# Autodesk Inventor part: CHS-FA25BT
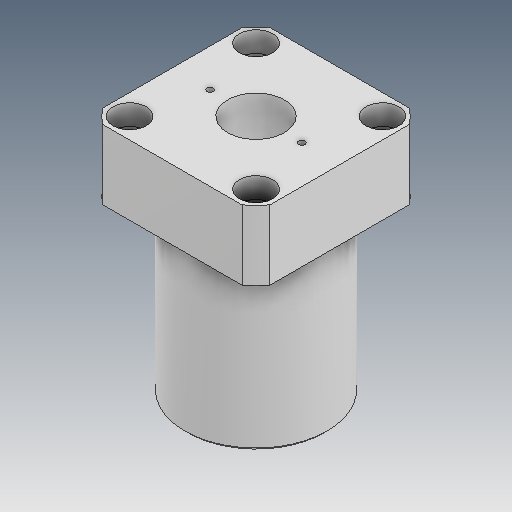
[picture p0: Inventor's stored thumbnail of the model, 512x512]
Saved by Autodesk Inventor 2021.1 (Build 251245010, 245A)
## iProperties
Created: 2021-05
Part Number: CHS-FA25BT
Material: Ogólny
Document SubType Name: Modeling
Designer: user
Density: 1 g/cm^3
Appearance: Domyślna
Author: user
Revision Number: ÈÎºÎ
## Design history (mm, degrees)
feature "_2.5 (2.5) Ö±¾¶¿×1"
node "Bryła1"
